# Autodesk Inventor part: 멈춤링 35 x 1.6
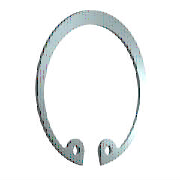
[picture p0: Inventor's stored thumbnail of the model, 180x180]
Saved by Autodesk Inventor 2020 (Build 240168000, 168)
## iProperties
Created: 2012-02
Part Number: 멈춤링 35 x 1.6
Material: 강철, 연강
Description: 리테이닝 링(C형)
Document SubType Name: Modeling
Standard: KS B 1336
Designer: mduedu
Standards Organization: KS
Language: ko-KR
Size Designation: 35x1.6
Categories: <MemberInstance><Categories><Category DisplayName="샤프트 부품" InternalName="7f7aeb1f-a693-4053-b835-cee3144e0d98" Mnemonic="SHFT"><Category DisplayName="써클립" Inter
Density: 1 g/cm^3
Appearance: 파란색 - 벽 페인트 - 광택
IsCustomPart: 1
Author: mduedu
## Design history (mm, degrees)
sketch "스케치1"
  geometry: L1 (0, 15.113)-(0, -73.177) reference; L2 (-45.5, 0)-(45.5, 0) reference; L3 (-4.964, 1)-(1.502, 1); L4 (0, -2.5)-(-5.307, -2.5); L5 (0, -17.5)-(-8.583, -33.888); L6 (-8.583, -33.888)-(-21.772, -26.981); L7 (-7.377, -31.585)-(-17.631, -26.214); L8 (-5.162, -32.745)-(-6.29, -34.898); L9 (5.162, -32.745)-(6.29, -34.898); C1 r 1.25 at (-7.377, -31.585); C2 r 1.25 at (7.377, -31.585); A1 r 15.875 centre (0, -18.375) between (11.82, -28.972) and (-11.82, -28.972); A2 r 18.5 centre (0, -17.5) between (6.29, -34.898) and (-6.29, -34.898); A3 r 2.5 centre (-7.377, -31.585) between (-5.162, -32.745) and (-8.668, -29.444); A4 r 2.5 centre (-9.959, -27.303) between (-11.82, -28.972) and (-8.668, -29.444); A5 r 2.5 centre (9.959, -27.303) between (8.668, -29.444) and (11.82, -28.972); A6 r 2.5 centre (7.377, -31.585) between (8.668, -29.444) and (5.162, -32.745); 3 further points
  constraints: 15 point on circle, 14 end point, 9 symmetric about line, 8 centre point, 6 tangent, 4 coincident, 4 point on line, 3 perpendicular, 1 parallel, 4 other
  dimensions: "d8" = 0.875 distance of A1.centre L5.start (= 0.25 x SRB1); "d38" = 3.5 distance between parallel lines of L4 L3 (= SRB1); "d39" = 17.5 distance from line of L5.start L2 (= 0.5 x WD); "d43" = 18.5 radius of A2 (= 0.5 x ND); "d45" = 2.6 distance between parallel lines of L7 L6 (= 0.5 x SRB2); "d46" = 2.5 radius of A4 (= SD5); "d47" = 6.29 distance from line of L1 L8.end (= 0.17 x ND); "d48" = 2.5 diameter of C1 (= SD5); "d49" = 2.5 radius of A3 (= SD5)
extrude "본체" new body sketch "스케치1" distance "d2" = 1.6 (= SD); taper "d3" = 0 deg
workaxis "Work Axis1"
workaxis "Work Axis2"
workplane "Work Plane1"
body "Solid1"
other parameters: "WD" = 35 [user parameter; used in 3 equation terms], "SD" = 1.6 [user parameter; used in 1 equation term], "SRB1" = 3.5 [user parameter; used in 2 equation terms], "ND" = 37 [user parameter; used in 2 equation terms], "SRB2" = 5.2 [user parameter; used in 1 equation term], "SD5" = 2.5 [user parameter; used in 3 equation terms], "d50" = 0, "d51" = 0, "d52" = 0, "d53" = 0, "WDMIN" = 34 [user parameter], "SD6" = 37.8 [user parameter], "WDMAX" = 35 (= WD) [user parameter], "NND" = 35 (= WD) [user parameter]
